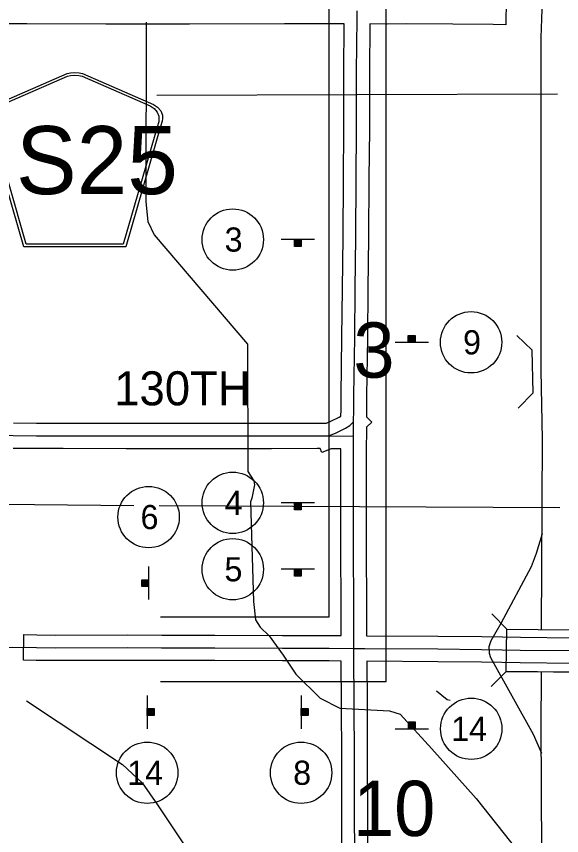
# Model space of a CAD drawing. Extents: x -2251611 to -2054719, y -2227156 to -2099355.
# Drawn here: x -2142114 to -2135345, y -2140286 to -2130114 of the extents above; entities that cross this region are included whole.
import ezdxf

# ---------------------------------------------------------------- set-up
doc = ezdxf.new("R2010")
doc.units = 0
for name, color, linetype in [('Default', 7, 'Continuous'), ('dsnTextFinalPlan', 7, 'Continuous'), ('dsnTextNote', 7, 'Continuous'), ('Level 35', 7, 'Continuous'), ('tdCoHydroRiver', 7, 'Continuous'), ('tdCoInt', 7, 'Continuous'), ('tdCoIntRamp', 7, 'Continuous'), ('tdCoSecRdTxt', 7, 'Continuous'), ('tdCoSecRteBand', 7, 'Continuous'), ('tdCoSectLinePart', 7, 'Continuous'), ('tdCoSectNmbr', 7, 'Continuous'), ('tdCoShieldCoRteHrd', 7, 'Continuous'), ('tdCoStrucDivPri', 7, 'Continuous'), ('tdCoStrucNonDivPri', 7, 'Continuous'), ('tdCoSurfConc', 7, 'Continuous'), ('tdCoSurfConcUnbanded', 7, 'Continuous'), ('tdCoSurfGravel', 7, 'Continuous')]:
    doc.layers.add(name, color=color, linetype=linetype)

msp = doc.modelspace()

# ---------------------------------------------------------------- linework, layer by layer
at = {"layer": 'Default'}
for p, q in [((-2138233, -2124556), (-2138233, -2137572)), ((-2137524, -2138371), (-2137524, -2125114)), ((-2138233, -2137572), (-2140325, -2137572)), ((-2140325, -2138371), (-2137524, -2138371))]:
    msp.add_line(p, q, dxfattribs=at)
at = {"layer": 'dsnTextFinalPlan'}
for p, q in [((-2138415, -2132885), (-2138828, -2132885)), ((-2138662, -2132891), (-2138578, -2132891)), ((-2138578, -2132895), (-2138662, -2132895)), ((-2138662, -2132899), (-2138578, -2132899)), ((-2138578, -2132903), (-2138662, -2132903)), ((-2138662, -2132906), (-2138578, -2132906)), ((-2138578, -2132909), (-2138662, -2132909)), ((-2138662, -2132914), (-2138578, -2132914)), ((-2138578, -2132918), (-2138662, -2132918)), ((-2138662, -2132922), (-2138578, -2132922)), ((-2138578, -2132927), (-2138662, -2132927)), ((-2138662, -2132932), (-2138578, -2132932)), ((-2138578, -2132939), (-2138662, -2132939)), ((-2138662, -2132942), (-2138578, -2132942)), ((-2138578, -2132948), (-2138662, -2132949)), ((-2138662, -2132952), (-2138578, -2132952)), ((-2138578, -2132956), (-2138662, -2132956)), ((-2138662, -2132960), (-2138578, -2132960)), ((-2138578, -2132965), (-2138662, -2132965)), ((-2137249, -2134081), (-2137165, -2134081)), ((-2137165, -2134086), (-2137249, -2134086)), ((-2137412, -2134161), (-2136999, -2134161)), ((-2137249, -2134090), (-2137165, -2134090)), ((-2137165, -2134094), (-2137249, -2134094)), ((-2137249, -2134098), (-2137165, -2134098)), ((-2137165, -2134104), (-2137249, -2134104)), ((-2137249, -2134107), (-2137165, -2134107)), ((-2137165, -2134114), (-2137249, -2134114)), ((-2137249, -2134119), (-2137165, -2134119)), ((-2137165, -2134124), (-2137249, -2134125)), ((-2137249, -2134128), (-2137165, -2134128)), ((-2137165, -2134132), (-2137249, -2134132)), ((-2137249, -2134137), (-2137165, -2134137)), ((-2137165, -2134140), (-2137249, -2134140)), ((-2137249, -2134143), (-2137165, -2134143)), ((-2137165, -2134147), (-2137249, -2134147)), ((-2137249, -2134151), (-2137165, -2134151)), ((-2137165, -2134155), (-2137249, -2134155)), ((-2138415, -2136154), (-2138828, -2136154)), ((-2138662, -2136160), (-2138578, -2136160)), ((-2138578, -2136164), (-2138662, -2136164)), ((-2138662, -2136168), (-2138578, -2136168)), ((-2138578, -2136172), (-2138662, -2136172)), ((-2138662, -2136176), (-2138578, -2136176)), ((-2138578, -2136179), (-2138662, -2136179)), ((-2138662, -2136184), (-2138578, -2136184)), ((-2138578, -2136188), (-2138662, -2136188)), ((-2138662, -2136191), (-2138578, -2136191)), ((-2138578, -2136196), (-2138662, -2136196)), ((-2138662, -2136201), (-2138578, -2136201)), ((-2138578, -2136208), (-2138662, -2136208)), ((-2138662, -2136211), (-2138578, -2136211)), ((-2138578, -2136217), (-2138662, -2136218)), ((-2138662, -2136221), (-2138578, -2136221)), ((-2138578, -2136226), (-2138662, -2136226)), ((-2138662, -2136229), (-2138578, -2136229)), ((-2138578, -2136234), (-2138662, -2136234)), ((-2140470, -2137356), (-2140470, -2136943)), ((-2138415, -2136979), (-2138828, -2136979)), ((-2138662, -2136985), (-2138578, -2136985)), ((-2138578, -2136989), (-2138662, -2136989)), ((-2138662, -2136993), (-2138578, -2136993)), ((-2138578, -2136997), (-2138662, -2136997)), ((-2138662, -2137000), (-2138578, -2137000)), ((-2138578, -2137003), (-2138662, -2137003)), ((-2138662, -2137009), (-2138578, -2137009)), ((-2138578, -2137012), (-2138662, -2137012)), ((-2138662, -2137016), (-2138578, -2137016)), ((-2138578, -2137021), (-2138662, -2137021)), ((-2138662, -2137026), (-2138578, -2137026)), ((-2138578, -2137033), (-2138662, -2137033)), ((-2138662, -2137036), (-2138578, -2137036)), ((-2140550, -2137193), (-2140550, -2137109)), ((-2140545, -2137109), (-2140545, -2137193)), ((-2140542, -2137193), (-2140542, -2137109)), ((-2140537, -2137109), (-2140537, -2137193)), ((-2140534, -2137193), (-2140534, -2137109)), ((-2140528, -2137109), (-2140527, -2137193)), ((-2140524, -2137193), (-2140524, -2137109)), ((-2140518, -2137109), (-2140518, -2137193)), ((-2140512, -2137193), (-2140512, -2137109)), ((-2140507, -2137109), (-2140507, -2137193)), ((-2140504, -2137193), (-2140504, -2137109)), ((-2140500, -2137109), (-2140500, -2137193)), ((-2140495, -2137193), (-2140495, -2137109)), ((-2140492, -2137109), (-2140492, -2137193)), ((-2140488, -2137193), (-2140488, -2137109)), ((-2140484, -2137109), (-2140484, -2137193)), ((-2140481, -2137193), (-2140481, -2137109)), ((-2140476, -2137109), (-2140476, -2137193)), ((-2138578, -2137042), (-2138662, -2137043)), ((-2138662, -2137046), (-2138578, -2137046)), ((-2138578, -2137050), (-2138662, -2137050)), ((-2138662, -2137054), (-2138578, -2137054)), ((-2138578, -2137059), (-2138662, -2137059)), ((-2140490, -2138546), (-2140490, -2138959)), ((-2138579, -2138546), (-2138579, -2138959)), ((-2140484, -2138793), (-2140484, -2138709)), ((-2140480, -2138709), (-2140480, -2138793)), ((-2140476, -2138793), (-2140476, -2138709)), ((-2140472, -2138709), (-2140472, -2138793)), ((-2140469, -2138793), (-2140469, -2138709)), ((-2140466, -2138709), (-2140466, -2138793)), ((-2140460, -2138793), (-2140460, -2138709)), ((-2140457, -2138709), (-2140457, -2138793)), ((-2140453, -2138793), (-2140453, -2138709)), ((-2140448, -2138709), (-2140448, -2138793)), ((-2140443, -2138793), (-2140443, -2138709)), ((-2140436, -2138709), (-2140436, -2138793)), ((-2140433, -2138793), (-2140433, -2138709)), ((-2140427, -2138709), (-2140426, -2138793)), ((-2140423, -2138793), (-2140423, -2138709)), ((-2140419, -2138709), (-2140419, -2138793)), ((-2140415, -2138793), (-2140415, -2138709)), ((-2140410, -2138709), (-2140410, -2138793)), ((-2138573, -2138793), (-2138573, -2138709)), ((-2138569, -2138709), (-2138569, -2138793)), ((-2138565, -2138793), (-2138565, -2138709)), ((-2138561, -2138709), (-2138561, -2138793)), ((-2138557, -2138793), (-2138557, -2138709)), ((-2138554, -2138709), (-2138554, -2138793)), ((-2138549, -2138793), (-2138549, -2138709)), ((-2138545, -2138709), (-2138545, -2138793)), ((-2138542, -2138793), (-2138542, -2138709)), ((-2138537, -2138709), (-2138537, -2138793)), ((-2138531, -2138793), (-2138531, -2138709)), ((-2138525, -2138709), (-2138525, -2138793)), ((-2138522, -2138793), (-2138522, -2138709)), ((-2138515, -2138709), (-2138515, -2138793)), ((-2138512, -2138793), (-2138512, -2138709)), ((-2138507, -2138709), (-2138507, -2138793)), ((-2138504, -2138793), (-2138504, -2138709)), ((-2138499, -2138709), (-2138499, -2138793)), ((-2137410, -2138960), (-2136998, -2138960)), ((-2137248, -2138880), (-2137164, -2138880)), ((-2137164, -2138885), (-2137248, -2138885)), ((-2137248, -2138888), (-2137164, -2138888)), ((-2137164, -2138893), (-2137248, -2138893)), ((-2137248, -2138896), (-2137164, -2138896)), ((-2137164, -2138902), (-2137248, -2138903)), ((-2137248, -2138906), (-2137164, -2138906)), ((-2137164, -2138912), (-2137248, -2138912)), ((-2137248, -2138918), (-2137164, -2138918)), ((-2137164, -2138923), (-2137248, -2138923)), ((-2137248, -2138926), (-2137164, -2138926)), ((-2137164, -2138930), (-2137248, -2138930)), ((-2137248, -2138935), (-2137164, -2138935)), ((-2137164, -2138938), (-2137248, -2138938)), ((-2137248, -2138942), (-2137164, -2138942)), ((-2137164, -2138945), (-2137248, -2138945)), ((-2137248, -2138949), (-2137164, -2138949)), ((-2137164, -2138954), (-2137248, -2138954))]:
    msp.add_line(p, q, dxfattribs=at)
for points in [[(-2138662, -2132886), (-2138577, -2132886), (-2138577, -2132970), (-2138662, -2132970)], [(-2137165, -2134160), (-2137249, -2134160), (-2137249, -2134076), (-2137165, -2134076)], [(-2138662, -2136155), (-2138577, -2136155), (-2138577, -2136240), (-2138662, -2136240)], [(-2138662, -2136980), (-2138577, -2136980), (-2138577, -2137064), (-2138662, -2137064)], [(-2140472, -2137109), (-2140472, -2137193), (-2140556, -2137193), (-2140556, -2137109)], [(-2140489, -2138793), (-2140489, -2138709), (-2140404, -2138709), (-2140404, -2138793)], [(-2138578, -2138793), (-2138578, -2138709), (-2138493, -2138709), (-2138493, -2138793)], [(-2137164, -2138958), (-2137248, -2138958), (-2137248, -2138874), (-2137164, -2138874)]]:
    msp.add_lwpolyline(points, close=True, dxfattribs=at)
at = {"layer": 'dsnTextNote'}
for centre in [(-2139428, -2132885), (-2136469, -2134161), (-2139428, -2136154), (-2140472, -2136331), (-2139428, -2136979), (-2136467, -2138960), (-2140490, -2139506), (-2138579, -2139506)]:
    msp.add_circle(centre, 381, dxfattribs=at)
at = {"layer": 'Level 35'}
msp.add_lwpolyline([(-2136026, -2137722), (-2134856, -2137734), (-2134861, -2138262), (-2136033, -2138252)], close=True, dxfattribs=at)
at = {"layer": 'tdCoHydroRiver'}
for points in [[(-2140503, -2130185), (-2140506, -2132418), (-2140481, -2132660), (-2140405, -2132826), (-2139244, -2134182), (-2139240, -2135765), (-2139165, -2135881), (-2139156, -2135931), (-2139189, -2136098), (-2139206, -2136140), (-2139170, -2137381), (-2139144, -2137606), (-2139086, -2137698), (-2138977, -2137806), (-2138802, -2138047), (-2138643, -2138280), (-2138342, -2138579), (-2138100, -2138704), (-2137483, -2138735), (-2137350, -2138777), (-2136957, -2139209), (-2136406, -2139824), (-2135729, -2140681), (-2135078, -2141005)], [(-2136900, -2138489), (-2136764, -2138596), (-2136729, -2138606)], [(-2141988, -2138612), (-2140797, -2139405), (-2140553, -2139630), (-2140360, -2139906), (-2139964, -2140499)]]:
    msp.add_lwpolyline(points, dxfattribs=at)
at = {"layer": 'tdCoInt'}
for points in [[(-2135593, -2137727), (-2135583, -2135365), (-2135600, -2134511), (-2135598, -2130378), (-2135576, -2129678), (-2135530, -2129293), (-2135473, -2128972), (-2135332, -2128427), (-2135169, -2127960), (-2134429, -2125998), (-2134077, -2125064)], [(-2135594, -2138325), (-2135593, -2138255)], [(-2135639, -2144316), (-2135635, -2143946), (-2135601, -2141706), (-2135589, -2140509), (-2135600, -2138905), (-2135594, -2138325)]]:
    msp.add_lwpolyline(points, dxfattribs=at)
at = {"layer": 'tdCoIntRamp'}
msp.add_lwpolyline([(-2135588, -2136541), (-2135661, -2136782), (-2135723, -2136950), (-2136101, -2137653), (-2136223, -2137866), (-2136247, -2137943), (-2136245, -2138023), (-2136229, -2138074), (-2135699, -2139026), (-2135597, -2139264)], dxfattribs=at)
at = {"layer": 'tdCoSecRteBand'}
for points in [[(-2136033, -2129901), (-2136036, -2130218), (-2136194, -2130216), (-2136695, -2130212), (-2136696, -2130212), (-2136696, -2130212), (-2137277, -2130207), (-2137511, -2130210), (-2137514, -2130210), (-2137517, -2130210), (-2137727, -2130205), (-2137727, -2130207), (-2137727, -2130207), (-2137732, -2130804), (-2137732, -2131513), (-2137732, -2131514), (-2137732, -2131514), (-2137737, -2132133), (-2137741, -2132858), (-2137741, -2132858), (-2137741, -2132859), (-2137749, -2133499), (-2137756, -2134103), (-2137756, -2134104), (-2137756, -2134104), (-2137766, -2134825), (-2137767, -2135001), (-2137768, -2135085), (-2137703, -2135151), (-2137768, -2135216), (-2137769, -2135326), (-2137770, -2135419), (-2137771, -2136072), (-2137770, -2136722), (-2137767, -2137441), (-2137766, -2137803), (-2137766, -2137805), (-2136880, -2137811), (-2136880, -2137811), (-2136880, -2137811), (-2136337, -2137815), (-2136336, -2137815), (-2136335, -2137815), (-2136080, -2137820), (-2135855, -2137824), (-2135197, -2137831)], [(-2140751, -2135166), (-2140471, -2135165), (-2140471, -2135165), (-2140471, -2135165), (-2139967, -2135165), (-2139481, -2135165), (-2138947, -2135165), (-2138393, -2135163), (-2138393, -2135163), (-2138266, -2135164), (-2138211, -2135142), (-2138106, -2135090), (-2138085, -2135077), (-2138084, -2134999), (-2138084, -2134999), (-2138084, -2134999), (-2138084, -2134990), (-2138083, -2134822), (-2138083, -2134821), (-2138083, -2134821), (-2138072, -2134100), (-2138066, -2133496), (-2138066, -2133496), (-2138066, -2133495), (-2138058, -2132855), (-2138054, -2132131), (-2138054, -2132130), (-2138054, -2132130), (-2138049, -2131512), (-2138049, -2130803), (-2138049, -2130803), (-2138049, -2130802), (-2138044, -2130207), (-2138786, -2130207), (-2139963, -2130210), (-2139964, -2130210), (-2139964, -2130210), (-2141004, -2130210), (-2141004, -2130210), (-2141005, -2130210), (-2141984, -2130206), (-2142615, -2130205)], [(-2142150, -2135161), (-2141863, -2135163), (-2141531, -2135163), (-2141531, -2135163), (-2141531, -2135163), (-2140751, -2135166)], [(-2138073, -2140436), (-2138074, -2139981), (-2138074, -2139981), (-2138074, -2139981), (-2138075, -2139326), (-2138078, -2138653), (-2138081, -2138121), (-2138081, -2138121), (-2138081, -2138119), (-2138230, -2138117), (-2138809, -2138118), (-2138810, -2138118), (-2138810, -2138118), (-2139651, -2138114), (-2140311, -2138113), (-2140311, -2138113), (-2140312, -2138113), (-2140739, -2138110), (-2141631, -2138113), (-2141632, -2138113), (-2141633, -2138113), (-2141867, -2138110), (-2142025, -2138107), (-2142021, -2137791), (-2141862, -2137793), (-2141630, -2137796), (-2140740, -2137794), (-2140739, -2137794), (-2140738, -2137794), (-2140310, -2137796), (-2139650, -2137798), (-2139650, -2137798), (-2139650, -2137798), (-2138809, -2137801), (-2138229, -2137800), (-2138228, -2137800), (-2138227, -2137800), (-2138083, -2137802), (-2138084, -2137442), (-2138084, -2137442), (-2138084, -2137442), (-2138087, -2136723), (-2138087, -2136723), (-2138087, -2136723), (-2138088, -2136072), (-2138088, -2136072), (-2138088, -2136071), (-2138087, -2135483), (-2138087, -2135483), (-2138087, -2135482), (-2138206, -2135482), (-2138324, -2135529), (-2138343, -2135480), (-2138378, -2135480), (-2138947, -2135482), (-2138947, -2135482), (-2138947, -2135482), (-2139481, -2135482), (-2139967, -2135482), (-2140470, -2135482), (-2140750, -2135483), (-2140750, -2135483), (-2140751, -2135483), (-2141532, -2135480), (-2141864, -2135480), (-2141864, -2135480), (-2141865, -2135480), (-2142152, -2135478)], [(-2135200, -2138148), (-2135859, -2138141), (-2135860, -2138141), (-2135861, -2138141), (-2136086, -2138137), (-2136340, -2138132), (-2136882, -2138127), (-2137764, -2138122), (-2137761, -2138651), (-2137761, -2138652), (-2137761, -2138652), (-2137758, -2139325), (-2137758, -2139325), (-2137758, -2139325), (-2137757, -2139980), (-2137756, -2140436)]]:
    msp.add_lwpolyline(points, dxfattribs=at)
at = {"layer": 'tdCoSectLinePart'}
for points in [[(-2140369, -2131091), (-2135396, -2131076)], [(-2145592, -2136138), (-2140657, -2136186)], [(-2140340, -2136189), (-2135368, -2136211)]]:
    msp.add_lwpolyline(points, dxfattribs=at)
at = {"layer": 'tdCoShieldCoRteHrd'}
for points in [[(-2142022, -2132977), (-2142454, -2131483), (-2142475, -2131414), (-2142479, -2131383), (-2142479, -2131342), (-2142456, -2131287), (-2142418, -2131242), (-2142367, -2131207), (-2141484, -2130825), (-2141444, -2130816), (-2141389, -2130812), (-2141334, -2130816), (-2141295, -2130825), (-2140411, -2131207), (-2140361, -2131242), (-2140322, -2131287), (-2140300, -2131342), (-2140300, -2131383), (-2140304, -2131414), (-2140324, -2131483), (-2140757, -2132977)], [(-2141991, -2132944), (-2142412, -2131490), (-2142431, -2131424), (-2142435, -2131394), (-2142435, -2131354), (-2142414, -2131302), (-2142377, -2131259), (-2142328, -2131225), (-2141480, -2130858), (-2141442, -2130850), (-2141389, -2130845), (-2141337, -2130850), (-2141298, -2130858), (-2140451, -2131225), (-2140402, -2131259), (-2140365, -2131302), (-2140344, -2131354), (-2140344, -2131394), (-2140347, -2131424), (-2140367, -2131490), (-2140788, -2132944)]]:
    msp.add_lwpolyline(points, close=True, dxfattribs=at)
at = {"layer": 'tdCoStrucDivPri'}
msp.add_lwpolyline([(-2135883, -2134977), (-2135700, -2134787), (-2135711, -2134259), (-2135901, -2134076)], dxfattribs=at)
at = {"layer": 'tdCoStrucNonDivPri'}
for p, q in [((-2136026, -2137722), (-2136211, -2137534)), ((-2136032, -2138250), (-2136220, -2138435))]:
    msp.add_line(p, q, dxfattribs=at)
msp.add_lwpolyline([(-2136026, -2137722), (-2134856, -2137734), (-2134861, -2138262), (-2136032, -2138250)], close=True, dxfattribs=at)
at = {"layer": 'tdCoSurfConc'}
msp.add_line((-2138229, -2137959), (-2137923, -2137962), dxfattribs=at)
for points in [[(-2141865, -2137951), (-2141631, -2137955), (-2140739, -2137952), (-2140311, -2137955), (-2139651, -2137956), (-2138809, -2137960), (-2138229, -2137959)], [(-2137923, -2137962), (-2137787, -2137964), (-2136881, -2137969), (-2136338, -2137974), (-2136083, -2137978), (-2135858, -2137983), (-2135199, -2137989), (-2134794, -2137992), (-2134794, -2137992)]]:
    msp.add_lwpolyline(points, dxfattribs=at)
at = {"layer": 'tdCoSurfConcUnbanded'}
msp.add_lwpolyline([(-2142422, -2137951), (-2142168, -2137947), (-2141865, -2137951)], dxfattribs=at)
at = {"layer": 'tdCoSurfGravel'}
for points in [[(-2137928, -2135325), (-2137927, -2135150), (-2137926, -2135000), (-2137924, -2134823), (-2137914, -2134102), (-2137907, -2133497), (-2137900, -2132857), (-2137896, -2132132), (-2137891, -2131513), (-2137891, -2130803), (-2137885, -2130141), (-2137885, -2130047)], [(-2138236, -2135323), (-2138146, -2135287), (-2138030, -2135229), (-2137973, -2135196), (-2137927, -2135150)], [(-2143150, -2135314), (-2142650, -2135316), (-2142152, -2135319), (-2141864, -2135321), (-2141864, -2135321)], [(-2141864, -2135321), (-2141532, -2135322), (-2140750, -2135324), (-2140471, -2135323), (-2139967, -2135323), (-2139481, -2135323), (-2138947, -2135323), (-2138378, -2135322), (-2138236, -2135323), (-2137928, -2135325)], [(-2137905, -2144316), (-2137904, -2143729), (-2137909, -2143094), (-2137910, -2142492), (-2137913, -2141884), (-2137915, -2141454), (-2137913, -2141195), (-2137914, -2140595), (-2137914, -2140538), (-2137915, -2139980), (-2137917, -2139326), (-2137919, -2138652), (-2137923, -2138040), (-2137923, -2137962), (-2137926, -2137441), (-2137928, -2136723), (-2137930, -2136072), (-2137928, -2135418), (-2137928, -2135325)]]:
    msp.add_lwpolyline(points, dxfattribs=at)

# ---------------------------------------------------------------- texts
at = {"layer": 'dsnTextNote'}
for s, p in [('3', (-2139529, -2133035)), ('9', (-2136569, -2134311)), ('4', (-2139529, -2136304)), ('6', (-2140573, -2136481)), ('5', (-2139531, -2137129)), ('14', (-2136717, -2139110)), ('14', (-2140739, -2139656)), ('8', (-2138678, -2139656))]:
    msp.add_text(s, height=300, dxfattribs=at).set_placement(p)
at = {"layer": 'tdCoSecRdTxt'}
msp.add_text('130TH', height=422.4, rotation=0.044, dxfattribs=at).set_placement((-2140900, -2134944))
at = {"layer": 'tdCoSectNmbr'}
for s, height, rotation, p in [('3', 686, 0.0193, (-2137930, -2134600)), ('10', 686.4, 0.0192, (-2137934, -2140292))]:
    msp.add_text(s, height=height, rotation=rotation, dxfattribs=at).set_placement(p)
at = {"layer": 'tdCoShieldCoRteHrd'}
msp.add_text('S25', height=844.8, dxfattribs=at).set_placement((-2142119, -2132321))

doc.saveas('drawing.dxf')
